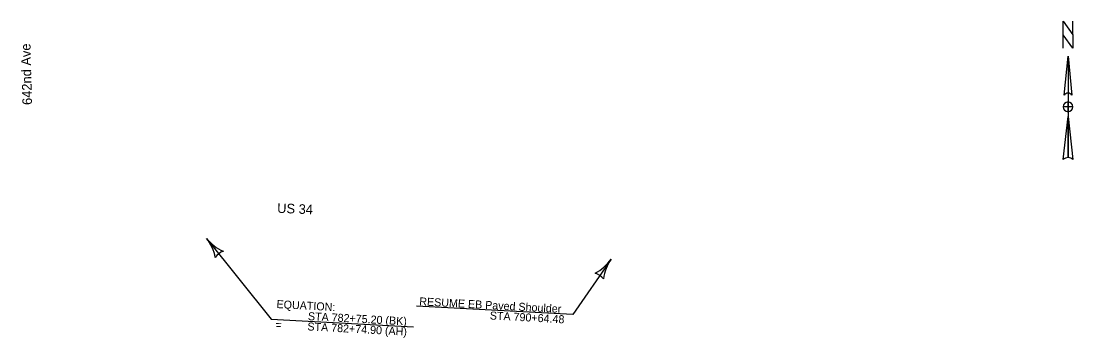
# Model space of a CAD drawing. Extents: x 22712865 to 22760106, y 6235088 to 6238602.
# Drawn here: x 22754964 to 22757015, y 6237226 to 6237844 of the extents above; entities that cross this region are included whole.
import ezdxf

# ---------------------------------------------------------------- set-up
doc = ezdxf.new("R2010")
doc.units = 0
for name, color, linetype in [('Contours Major', 7, 'Continuous'), ('Default', 7, 'Continuous'), ('Draft_3', 7, 'Continuous'), ('dsnTextOdd', 7, 'Continuous')]:
    doc.layers.add(name, color=color, linetype=linetype)

msp = doc.modelspace()

# ---------------------------------------------------------------- linework, layer by layer
at = {"layer": 'Contours Major'}
msp.add_lwpolyline([(22755325.7, 6237420.1), (22755451.8, 6237262.4), (22755729.4, 6237247.5)], dxfattribs=at)
for centre, radius, start, end in [((22755259.3, 6237367.1), 85, 10.562, 38.6344), ((22755392.1, 6237473.2), 85, 218.6344, 246.7069), ((22755370.2, 6237364.5), 32.8, 110.9011, 146.3678)]:
    msp.add_arc(centre, radius, start, end, dxfattribs=at)
at = {"layer": 'Draft_3'}
msp.add_lwpolyline([(22756114.4, 6237379.7), (22756039.6, 6237271.4), (22755735.1, 6237287.7)], dxfattribs=at)
for centre, radius, start, end in [((22756044.5, 6237428), 85, 297.2646, 325.3371), ((22756184.3, 6237331.3), 85, 145.3371, 173.4096), ((22756073.9, 6237321), 32.8, 37.6038, 73.0705)]:
    msp.add_arc(centre, radius, start, end, dxfattribs=at)
at = {"layer": 'dsnTextOdd'}
for p, q in [((22757005.5, 6237775.4), (22757013.1, 6237699.4)), ((22757005.5, 6237775.4), (22757005.5, 6237577.7)), ((22756997.9, 6237699.4), (22756997.9, 6237699.4)), ((22756998.2, 6237700.1), (22756999.6, 6237701.7)), ((22757005.5, 6237667.1), (22757005.5, 6237667.1)), ((22756996, 6237573.9), (22757005.5, 6237657.5))]:
    msp.add_line(p, q, dxfattribs=at)
msp.add_lwpolyline([(22757015, 6237790.7), (22756996, 6237817.3), (22756996, 6237843.9), (22757015, 6237817.3)], close=True, dxfattribs=at)
for points in [[(22756996, 6237790.7), (22756996, 6237843.9), (22757015, 6237817.3), (22757015, 6237843.9)], [(22756997.9, 6237699.4), (22757005.5, 6237775.4), (22757005.5, 6237703.2)], [(22757015, 6237676.6), (22757005.5, 6237676.6), (22757005.5, 6237686.1)], [(22757005.5, 6237667.1), (22757005.5, 6237676.6), (22756996, 6237676.6)], [(22757005.5, 6237577.7), (22757005.5, 6237657.5), (22757015, 6237573.9)]]:
    msp.add_lwpolyline(points, dxfattribs=at)
for centre, radius, start, end in [((22757005.5, 6237693.7), 9.51, 90.0204, 143.1257), ((22757005.5, 6237693.7), 9.5, 36.8481, 90.0218), ((22757005.5, 6237676.6), 9.51, 90, 180), ((22757005.5, 6237676.6), 9.51, 0, 90), ((22757005.5, 6237676.6), 9.51, 180, 270), ((22757005.5, 6237676.6), 9.51, 270, 360), ((22757005.5, 6237563.9), 13.8, 89.9894, 133.619), ((22757005.5, 6237563.9), 13.8, 46.4021, 90.0006)]:
    msp.add_arc(centre, radius, start, end, dxfattribs=at)

# ---------------------------------------------------------------- texts
at = {"layer": 'Contours Major'}
for s, height, p in [('EQUATION:', 15.6, (22755461.9, 6237284.3)), ('STA 782+75.20 (BK)', 15.601, (22755523.1, 6237260.8)), ('=', 15.6, (22755459.8, 6237244)), ('STA 782+74.90 (AH)', 15.601, (22755522.1, 6237240.7))]:
    msp.add_text(s, height=height, rotation=356.9456, dxfattribs=at).set_placement(p)
at = {"layer": 'Default'}
for s, rotation, p in [('642nd Ave', 91.5318, (22754985.6, 6237680.5)), ('US 34', 357.6333, (22755463.2, 6237469.9))]:
    msp.add_text(s, height=18.75, rotation=rotation, dxfattribs=at).set_placement(p)
at = {"layer": 'Draft_3'}
for s, p in [('RESUME EB Paved Shoulder', (22755740.2, 6237289.6)), ('STA 790+64.48', (22755877.7, 6237262.1))]:
    msp.add_text(s, height=15.601, rotation=356.9456, dxfattribs=at).set_placement(p)

doc.saveas('drawing.dxf')
